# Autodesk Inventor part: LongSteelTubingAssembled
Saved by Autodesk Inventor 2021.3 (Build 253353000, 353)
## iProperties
Created: 2022-04
Part Number: LongSteelTubingAssembled
Material: Generic
Document SubType Name: Modeling
Designer: Administrator
Density: 1 g/cm^3
Appearance: Default
Title: LongSteelTubingAssembled v6
Author: Administrator
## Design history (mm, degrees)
feature "Body2"
feature "Body9"
body "Solid1"
body "Solid2"
